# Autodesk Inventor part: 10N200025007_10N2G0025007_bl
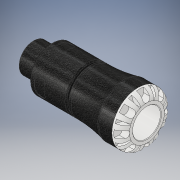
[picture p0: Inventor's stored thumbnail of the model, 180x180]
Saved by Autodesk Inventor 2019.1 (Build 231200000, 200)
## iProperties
Created: 2016-12
Part Number: 10N200025007_10N2G0025007_bl
Material: PVC-Piping
Description: PLASSON MALE ADAPTOR 25X3/4" SERIES 1
Document SubType Name: Modeling
Designer: KIM
Mass: 61.7504 g
Surface Area: 140.097 cm^2
Volume: 44.1074 cm^3
Density: 1.4 g/cm^3
Appearance: Black Cast
Author: KIM
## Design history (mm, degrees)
derived "10N20.ipt"
feature "Solid1::10N20.ipt" dims "ScaleForDerivedMember" = 10
tag "TaggingFeature1"
body "Solid1"
other parameters: "d0" = 102 [user parameter], "d1" = 20.16 [user parameter], "d2" = 25 [user parameter], "d3" = 31.25 [user parameter], "d4" = 47 [user parameter], "d6" = 48 [user parameter], "d8" = 39.95 [user parameter], "d13" = 6.3 [user parameter], "d14" = 6.3 [user parameter], "d15" = 0 [user parameter], "d17" = 360 deg [user parameter], "d19" = 8 deg [user parameter], "d20" = 0.5 [user parameter], "d21" = 0.5 [user parameter], "d22" = 8 deg [user parameter], "d24" = 0 [user parameter], "d26" = 360 deg [user parameter], "d32" = 0.925 [user parameter], "d33" = 4.7 [user parameter], "d34" = 26.441 [user parameter], "d35" = 3.125 [user parameter], "d38" = 17 [user parameter], "d39" = 0.79323 [user parameter], "d42" = 8.75 [user parameter], "d43" = 5.75 [user parameter], "d45" = 12.348 [user parameter], "d46" = 0 [user parameter], "d59" = 360 deg [user parameter], "d61" = 7.4375 [user parameter], "d62" = 0.5 [user parameter], "d64" = 0 [user parameter], "d65" = 0.47 [user parameter], "d69" = 2 [user parameter], "d70" = 1.53 [user parameter], "d71" = 3 [user parameter], "d73" = 1 [user parameter], "d_" = 25 [user parameter], "E_" = 47 [user parameter], "H_" = 102 [user parameter], "l_" = 48 [user parameter], "R_" = 26.441 [user parameter], "l_2" = 17 [user parameter], "d9" = 7.875 [user parameter], "d11" = 47 [user parameter], "d12" = 31.25 [user parameter]
